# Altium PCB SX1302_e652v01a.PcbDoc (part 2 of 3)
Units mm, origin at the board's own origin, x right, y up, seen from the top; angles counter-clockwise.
Board outline 70.5 x 56 mm, 6 copper layers (Top Layer, MidLayer1 - GND, MidLayer2, MidLayer3, MidLayer4, Bottom Layer), stack 0.992 mm thick; 264 components, 191 nets, 862 pads, 1252 vias.
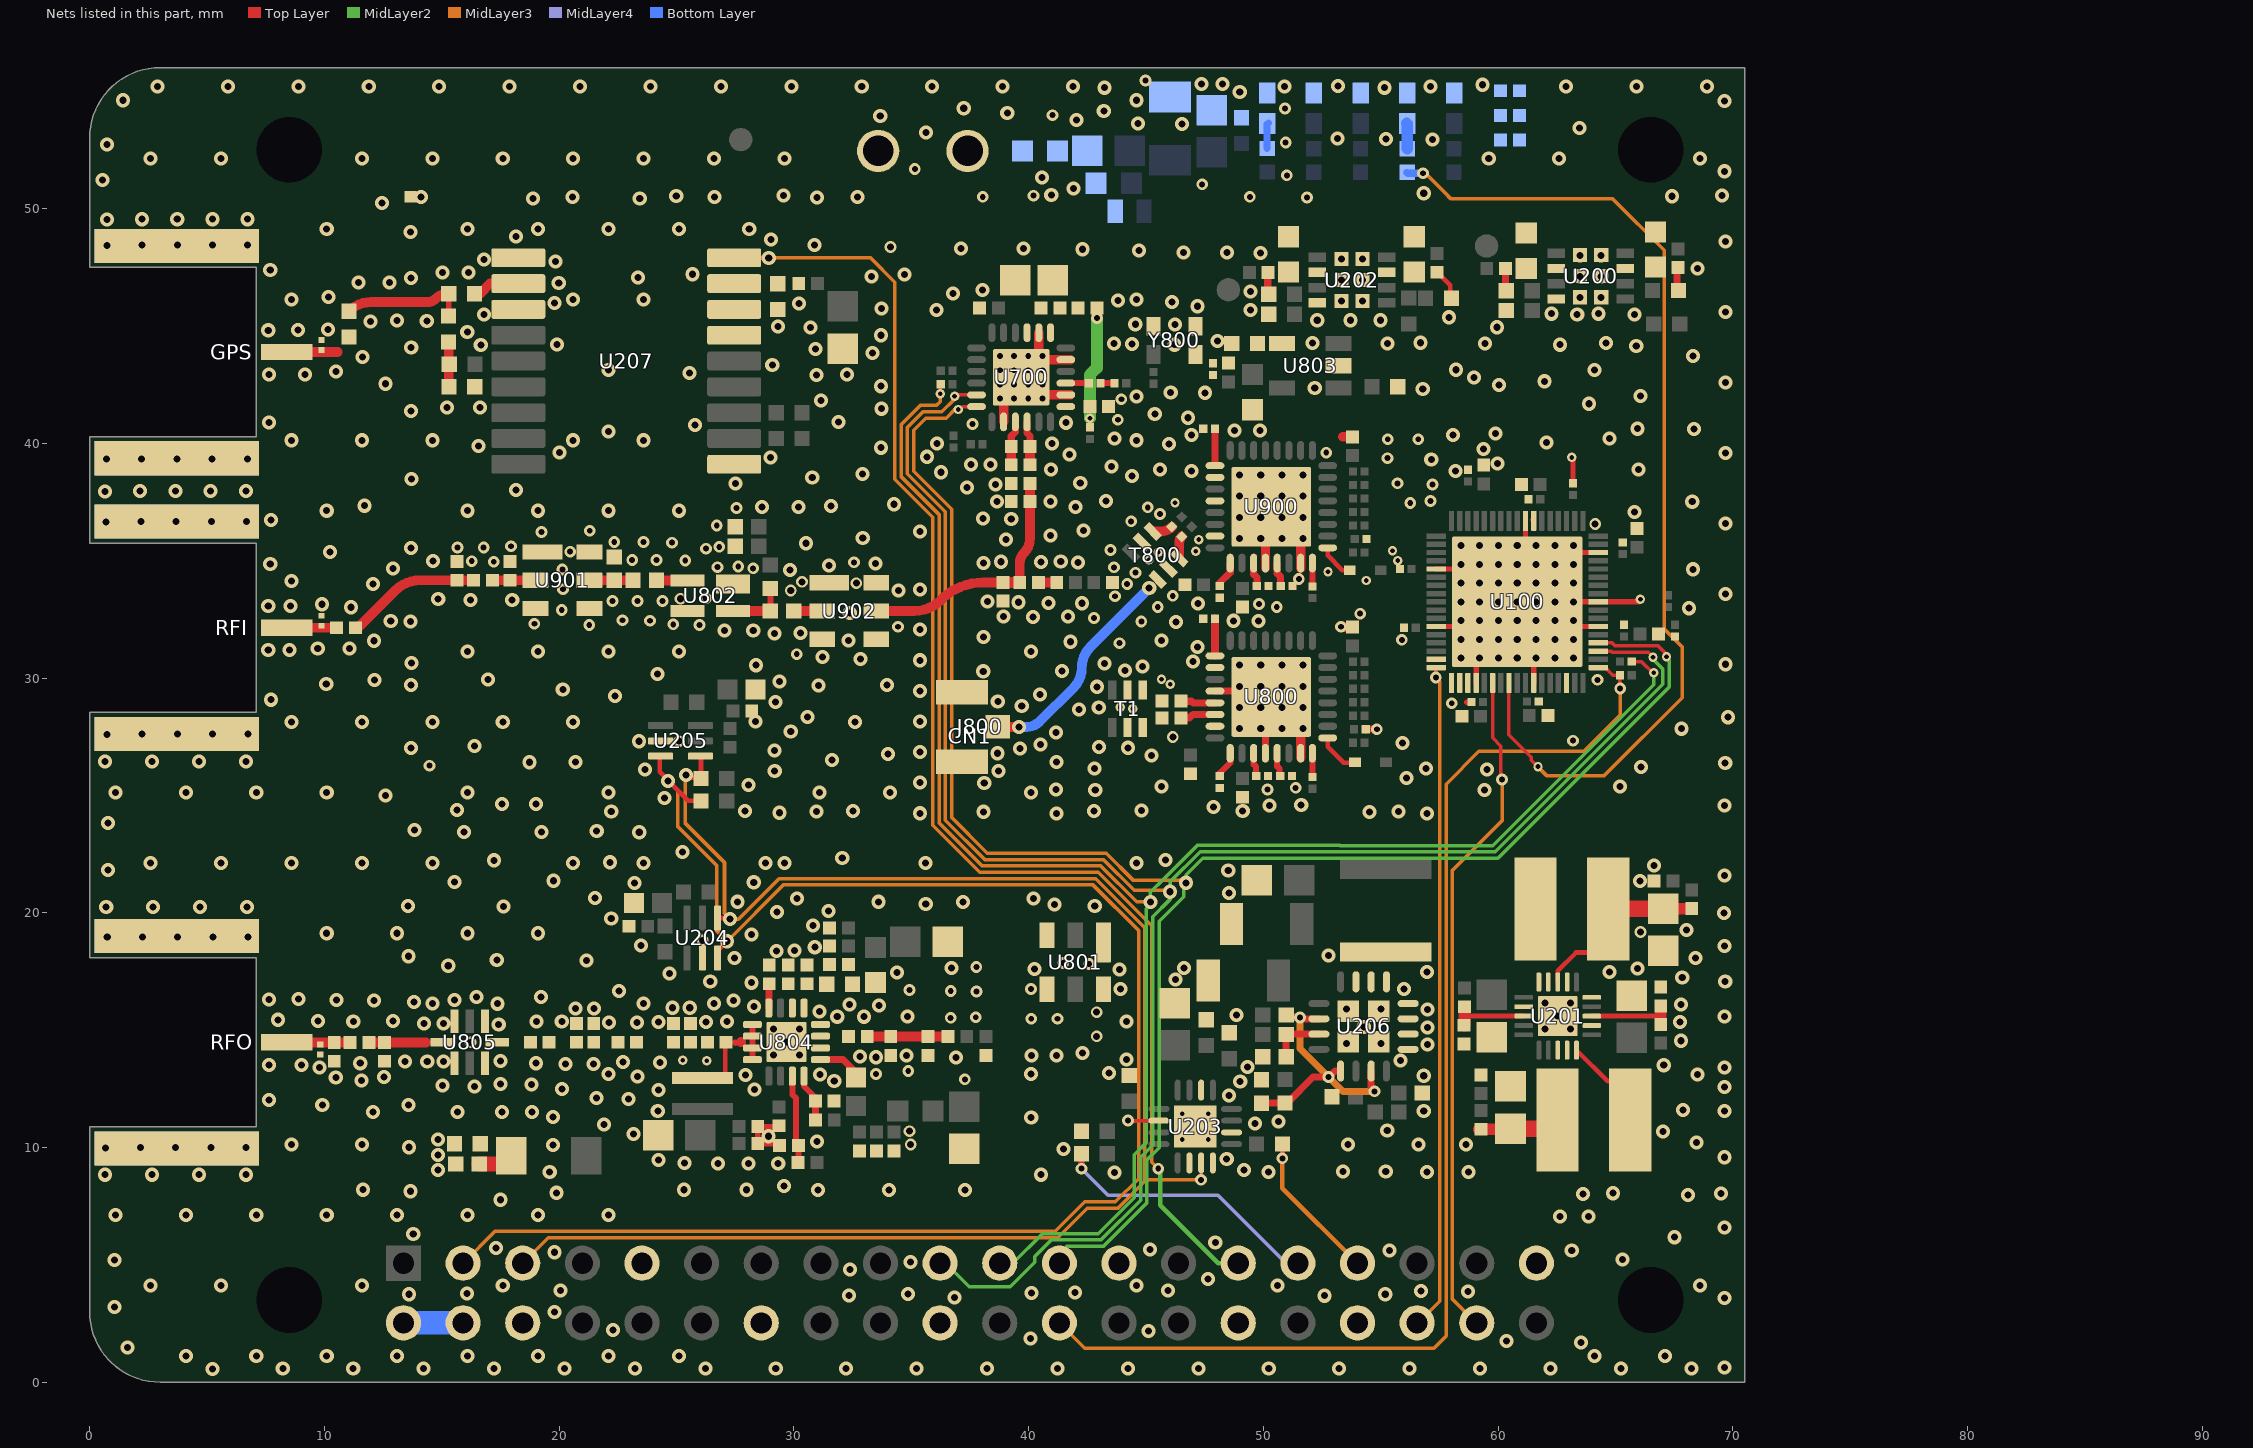
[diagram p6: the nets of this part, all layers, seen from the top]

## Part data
821M 915M Other R2 R10 R11 R12 R15 R100 R101 R102 R103 R104 R105 R106 R108 R110 R111 R112 R113 R114 R115 R120 R121 R122 R123 R124 R125 R205 R208 R209 R210 R211 R212 R214 R215 R216 R701 R702 R703 R704 R705 R713 R813 R814 R815: "Resistor SMD - IEC symbol version"
C2 C7 C8 C9 C10 C11 C12 C13 C14 C18 C19 C22 C23 C24 C25 C26 C27 C28 C31 C32 C33 C36 C37 C38 C39 C40 C41 C42 C43 C44 C45 C46 C51 C52: library part 70001226, "Ceramic Capacitor SMD"
C34 C100 C101 C102 C103 C104 C105 C106 C107 C108 C109 C110 C111 C112 C113 C201 C202 C203 C204 C212 C213 C215 C216 C217 C218 C220 C221 C222 C223 C708 C711 C712 C713 C716 C717 C718 C800 C801 C802 C803 C804 C805 C806 C807 C808 C809 C810 C813 C814 C815 C816 C838 C841 C842 C900 C901 C903 C904 C905 C906 C907 C908: "Capacitor SMD"
C35 C47 C48: library part Capacitor_p, "CAP TANT 120UF 6.3V", Manufacturer=Vishay
C200 C205 C206 C207 C209 C210 C211 C811 C812 C817: library part 70001485, "Ceramic Capacitor SMD"
C208 C219: library part Capacitor_p, "CAP TANT 10UF 6.3V", Manufacturer=Vishay
C214: library part CAP, "Ceramic Capacitor SMD"
CN1: library part RPI, "Raspberry PI 2x20p connector - Header male or receptacle"
D1 D3 D5 D802: library part RClamp0531T, "Ultra Low Capacitance 1-line ESD Protection"
D2 D800 D900: "Schottky Diode"
F200: "Fuse"
"Fiducial Mark1" "Logo ESD 1" "Logo ESD 2" "Logo LoRa 1" "Logo LoRa 2" "Logo Recycling2" "Logo Semtech 1" "Logo Semtech 2": library part Logo, "Schematic symbol for Logo"
GPS RFI RFO: "SMA Right Angle Jack, Edge Mount, Up to 18 GHz, -65 to 165 degC"
J800: library part 1909763-1, "Ultra Miniature Coaxial Connector Jack, 60 V, 50 Ohm, -40 to 90 degC, RoHS, Tape and Reel", Maximum Frequency="6 GHz", Operating Temperature Range="- 40 C to + 90 C", Supplier Part Number 1=62X0488
L1: library part L_LPS4018-102NLB, "Shielded Power Inductor 1uH isat 2.5A", Manufacturer=Coilcraft
L2 L10: library part L_MPZ1608S300A, "Ferrite Bead 30Ohm 10mOhm DC 5A", Manufacturer=TDK
L3: library part L_LQW15AN11NJ80D_11NH_0402, "Inductance wirewound 0402", Manufacturer=Murata
L4: library part L_LQW15AN8N7J80D_8_7NH_0402, "Inductance wirewound 0402", Manufacturer=Murata
L7: library part L_LQW15AN3N6D80D_3_6NH_0402, "Inductance wirewound 0402", Manufacturer=Murata
L8: library part L_FBMH4532HM681, "Ferrite Bed 680 Ohm 1812", Manufacturer="Tayio Yuden"
L11: library part L_LQW15AN1N6D80D_1_6NH_0402, "Inductance wirewound 0402", Manufacturer=Murata
L12: library part L_LQW15ANR10J00D_100NH_0402, "100nH Inductance wirewound 0402", Manufacturer=Murata
L13: library part L_LQW15AN10NJ80D_10NH_0402, "10nH Inductance wirewound 0402", Manufacturer=Murata
L15: library part L_LQW15AN3N6D80D_3_6NH_0402, "3.6nH Inductance wirewound 0402", Manufacturer=Murata
L202: "Inductor SMD"
P1: library part "Header 2", "Header, 2-Pin"
P200 P201: library part "Testpunkt SMD"
R1 R9 R13 R300: library part 70001106, "SMD Resistor"
R3 R4 R5 R6 R7 R8 R14 R19 R200 R201 R202 R203 R204 R206 R207 R213 R218 R219 R220: library part Res, "SMD Resistor"
R217: "Resistor"
"RF Shield": library part Shield, "RF Shield - EMI Gasket - Standard Surface Mount Shields"
RV1: library part RV_82536259, "Varistor 5.5V 0603", Manufacturer=Würth
T1 T800: library part T_BALUN_HHM1564A4, "High Frequency Balun - TDK HHM Series", 490MHz MPN=HHM1591D1, Manufacturer=TDK
U100: "SX1302 - Base Band Processor for Data Concentrator for Long Range Communication Network;"
U200 U202: "SC4212 - Very Low Input /Very Low Dropout  1Amp Regulator With Enable", Manufacturer=Semtech
U201: "SC284 - Dual Channel 2.5MHz, 1.8A  Synchronous Step-Down Regulator"
U204 U205: library part STTS751, "2.25 V low-voltage local digital temperature sensor"
U206: "6.5 V, 4 A, High Efficiency,   Step-Down DC-to-DC Regulator", Manufacturer="Analog Devices"
U207: library part MAX-7Q, "MAX-7Q; U-Blox; 7 GPS/GNSS modules"
U700: library part SX126x, "SX1261/2 - Ultra low power RF transceiver"
U800 U900: library part SX1257, "SX1257 RF Front-End Transceiver - I/Q New Pinout"
U801 U901 U902: "SAW Filter - Bandpass - TEMEX type"
U802: "Low Noise Amplifier", Manufacturer=RFMD
U803: library part LP2985-33, "LDO 150mA w/ Enable", Manufacturer=TI
U804: "RF5110G - General Power Amplifier", Manufacturer=RFMD
U805: library part FILT_0915LP15A026, "RF Filter - Lowpass", Manufacturer="Johanson Technology"

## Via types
v1: diameter 0.6, hole 0.3, Top Layer to Bottom Layer, tented both sides, 827 vias
v2: diameter 0.5, hole 0.25, Top Layer to Bottom Layer, tented both sides, 168 vias
v3: diameter 0.6, hole 0.3, Top Layer to Bottom Layer, tented top, 86 vias
v4: diameter 0.4, hole 0.2, Top Layer to Bottom Layer, tented both sides, 59 vias
v5: diameter 0.6, hole 0.3, Top Layer to Bottom Layer, 48 vias
v6: diameter 0.6, hole 0.3, Top Layer to Bottom Layer, tented bottom, 21 vias
v7: diameter 0.5, hole 0.3, Top Layer to Bottom Layer, tented both sides, 18 vias
v8: diameter 0.5, hole 0.25, Top Layer to Bottom Layer, tented top, 16 vias
v9: diameter 0.5, hole 0.3, Top Layer to Bottom Layer, 5 vias
v10: diameter 0.5, hole 0.2, Top Layer to Bottom Layer, 4 vias

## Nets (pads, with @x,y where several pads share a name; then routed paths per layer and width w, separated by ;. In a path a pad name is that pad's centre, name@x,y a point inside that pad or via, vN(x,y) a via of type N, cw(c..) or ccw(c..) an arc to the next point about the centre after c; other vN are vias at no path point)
AD5338R_LDAC_N: CN1.31 R219.2 | length 11.6
  Top Layer w0.25: v2(42.251,9.102) 42.252,9.104 R219.2@42.252,9.733 R219.2@42.252,9.783
  MidLayer4 w0.15: v2(42.251,9.102) 43.383,7.97 48.067,7.97 50.962,5.075 CN1.31@51.471,5.075
AD5338R_RESET_N: CN1.33 R220.2 | length 6.4
  Top Layer w0.2: v2(50.81,9.542) 50.812,9.544 R220.2@50.812,10.15
  MidLayer3 w0.2: v2(50.81,9.542) 50.81,8.276 CN1.33@54.011,5.075
CONFIG_OK: R105.2 U100.59 | length 43.8
  Top Layer w0.15: U100.59@60.449,29.825 60.449,29.798 60.449,27.59 61.414,26.625 61.414,26.497 61.681,26.23 v4(61.701,26.23)
  MidLayer3 w0.15: v2@56.78,51.505 v2(56.801,51.505) 56.801,51.424 56.841,51.465 56.891,51.515 57.701,50.705 57.995,50.411 64.881,50.411 67.072,48.22 67.072,32.093 67.838,31.326 67.838,29.161 64.525,25.848 62.063,25.848 61.701,26.211 v4(61.701,26.23) 61.681,26.23 v4@61.617,26.294
  Bottom Layer w0.3: R105.2@56.106,51.542 56.116,51.532 56.142,51.505 v2(56.801,51.505)
GND: 821M.1 821M.2 915M.1 915M.2 "RF Shield.1" C2.1 C7.1 C8.1 C9.1 C10.1 C11.1 C12.1 C13.1 C14.1 C18.1 C19.1 C22.1 C23.1 C24.1 C25.1 C28.1 C31.1 C32.1 C33.1 C34.2 C35.2 C36.1 C37.1 C38.1 C39.1 C40.1 C41.1 C42.1 C43.1 C44.1 C47.2 C48.2 C51.1 C52.1 C100.1 C101.1 C102.1 C103.1 C104.1 C105.1 C106.1 C107.1 C108.1 C109.1 C110.1 C111.1 C112.1 C113.1 C200.2 C201.2 C202.2 C203.2 C204.2 C205.2 C206.2 C207.2 C208.2 C209.2 C210.2 C211.2 C212.2 C213.2 C215.2 C216.1 C217.1 C218.2 C219.2 C220.1 C221.1 C222.2 C223.2 C712.1 C713.1 C716.1 C717.1 C718.1 C800.1 C803.1 C804.2 C805.2 C806.1 C807.1 C808.1 C811.1 C812.1 C814.2 C817.1 C838.1 C841.2 C842.2 C900.1 C903.1 C904.2 C905.2 C906.1 C907.1 C908.1 CN1.6 CN1.9 CN1.14 CN1.20 CN1.25 CN1.30 CN1.34 CN1.39 CONFIG_OK.2 D1.2 D3.2 D5.2 D802.2 DC5V.2 GPS.MP J800.1 J800.3 L13.1 L800.1 Other.1 Other.2 P1.2 R6.1 R7.1 R11.1 R12.1 R13.1 R100.1 R101.1 R202.1 R206.1 R218.1 R813.2 R814.2 RFI.MP RFO.MP RV1.1 RX_ON.2 T1.2 T1.5 T800.2 T800.5 TX_ON.2 U100.6 U100.9 U100.15 U100.24 U100.25 U100.39 U100.46 U100.55 U100.62 U100.69 U200.8 U200.9 U201.2 U201.9 U201.12 U201.15 U201.17 U201.19 U201.21 U202.8 U202.9 U203.2 U203.10 U203.12 U203.14 U203.17 U204.5 U205.5 U206.5 U206.6 U206.7 U206.8 U206.17 U207.1 U207.10 U207.12 U700.2 U700.5 U700.8 U700.20 U700.25 U800.4 U800.7 U800.26 U800.28 U800.31 U800.33 U801.1 U801.3 U801.4 U801.6 U802.2 U802.4 U803.2 U804.2 U804.4 U804.17 U805.1 U805.3 U805.5 U805.7 U900.4 U900.7 U900.26 U900.28 U900.31 U900.33 U901.1 U901.3 U901.4 U901.6 U902.1 U902.3 U902.4 U902.6 VCCIO33.2 Y800.1 Y800.2 | length 28.2
  Top Layer w0.2: U100.24@61.463,36.75 U100.24@61.515,36.698 ; v4@63.091,39.451 v4(63.141,39.4)
  Top Layer w0.23: C14.1@28.496,10.089 28.463,10.122 C14.1@28.463,10.169 ; C19.1@29.376,10.93 29.376,10.894 28.924,10.894 C13.1@28.463,10.894 C14.1@28.463,10.169 ; C2.1@29.461,10.038 29.403,10.096 29.33,10.169 28.924,10.169 C14.1@28.463,10.169 ; U100.46@57.365,32.198 58.365,32.198 U100.69@58.415,32.248 ; U100.39@57.365,34.648 U100.69@58.415,34.648 ; 58.667,28.978 C108.1@58.862,28.978 ; U100.55@59.065,29.798 U100.69@59.065,30.848 ; U100.69@61.165,35.648 U100.25@61.165,36.698 ; U100.62@61.515,29.798 U100.69@61.515,30.773 ; U100.69@63.09,32.198 63.215,32.198 U100.6@64.265,32.198 ; U100.69@63.115,35.348 63.215,35.348 U100.15@64.265,35.348 ; v4@63.182,39.458 63.19,39.45 63.192,39.448 63.192,39.4 R100.1@63.192,38.303 ; U100.69@63.326,33.255 63.333,33.248 U100.9@64.265,33.248 65.994,33.248 v4@66.001,33.255
  Top Layer w0.3: U800.28@47.939,29.448 48.989,29.448 49.889,29.448 50.089,29.448 U800.33@50.339,29.198 ; U800.4@50.089,26.798 50.089,27.848 U800.33@50.089,27.948 ; U800.33@51.639,29.423 U800.33@51.664,29.448 ; U800.33@51.664,28.923 U800.33@51.689,28.948 ; R813.2@54.364,27.798 54.377,27.811 54.389,27.823 v2@54.664,27.823
  Top Layer w0.4: U700.20@38.935,40.914 38.935,41.914 U700.25@38.935,41.939 ; U700.25@40.41,43.564 40.585,43.564 U700.5@41.585,43.564 U700.5@41.785,43.564 ; U700.25@40.41,43.714 40.435,43.739 U700.8@40.435,44.714 ; U700.25@40.585,42.064 U700.2@41.585,42.064 U700.2@41.785,42.064 ; U900.4@50.089,34.698 U900.4@50.089,34.898 50.089,35.948 U900.33@50.089,36.25 ; U800.33@51.539,27.898 51.589,27.848 U800.7@51.589,26.798 U800.7@51.589,26.598 ; U900.33@51.539,35.998 51.589,35.948 U900.7@51.589,34.898 U900.7@51.589,34.673 ; v2@53.389,32.173 C800.1@53.789,32.173 ; 53.389,40.273 C900.1@53.789,40.273
  other v1: 5.229,0.564 8.229,0.589 11.229,0.589 14.229,0.589 17.229,0.589 20.229,0.589 23.229,0.589 26.229,0.589 29.229,0.589 32.229,0.589 35.229,0.589 38.229,0.589 41.229,0.589 44.229,0.589 47.229,0.589 50.229,0.589 53.229,0.589 56.229,0.589 59.229,0.589 62.229,0.589 65.229,0.589 68.229,0.589 69.644,0.64 4.101,1.13 7.101,1.13 10.101,1.13 13.101,1.13 16.101,1.13 19.101,1.13 22.101,1.13 25.101,1.13 64.101,1.13 67.101,1.13 1.623,1.478 63.527,1.702 60.363,1.767 40.072,1.862 45.108,2.195 22.292,2.222 19.809,3.002 1.064,3.205 69.644,3.589 36.843,3.614 32.352,3.694 52.602,3.69 13.6,3.754 55.192,3.754 16.071,3.781 34.87,3.767 40.118,3.805 41.984,3.819 56.712,3.888 58.725,3.87 20.06,3.908 45.934,3.92 2.601,4.13 5.601,4.13 11.601,4.13 17.601,4.13 44.601,4.13 50.601,4.13 68.601,4.13 47.639,4.409 32.393,4.805 34.973,5.127 1.064,5.205 65.301,5.236 19.807,5.541 55.373,5.617 63.137,5.624 45.178,5.652 17.318,5.719 47.952,5.955 67.512,6.182 13.787,6.313 69.644,6.589 62.633,7.066 63.853,7.066 1.101,7.13 4.101,7.13 7.101,7.13 10.101,7.13 13.101,7.13 16.101,7.13 19.101,7.13 22.101,7.13 17.498,7.777 63.624,8.031 64.894,8.057 11.649,8.206 25.328,8.204 27.989,8.204 31.02,8.201 34.054,8.201 37.284,8.201 29.579,8.36 0.657,8.844 2.657,8.844 4.657,8.844 6.657,8.844 40.522,8.844 43.654,8.937 19.6,8.963 50.213,8.958 56.963,8.966 58.73,8.966 53.398,8.976 55.214,8.976 49.175,9.043 26.769,9.327 28.064,9.327 29.334,9.327 25.346,9.352 24.229,9.475 48.439,9.517 69.644,9.589 41.491,9.946 19.733,10.103 8.601,10.13 11.601,10.13 53.601,10.13 56.601,10.13 58.625,10.132 68.454,10.21 30.987,10.267 28.924,10.484 23.162,10.571 67.03,10.69 55.277,10.723 21.917,10.978 49.636,11.035 50.64,11.108 40.111,11.281 19.733,11.308 12.064,11.525 15.669,11.525 17.573,11.525 18.853,11.51 24.203,11.562 56.832,11.562 67.869,11.604 9.912,11.81 13.586,11.816 7.651,12.019 22.953,12.063 21.587,12.121 48.532,12.222 24.229,12.451 28.318,12.476 20.123,12.502 69.644,12.589 16.397,12.607 15.033,12.654 18.818,12.68 17.498,12.705 49.014,12.822 31.721,12.835 11.579,12.857 10.487,12.984 12.545,13.01 23.34,13.035 56.832,13.06 27.937,13.086 22.101,13.13 31.119,13.118 40.101,13.13 68.501,13.112 43.416,13.186 9.802,13.416 49.321,13.437 67.056,13.509 7.642,13.518 9.02,13.521 20.267,13.559 21.459,13.557 11.529,13.594 19.022,13.594 24.305,13.619 22.73,13.645 13.433,13.675 14.383,13.675 15.069,13.675 17.498,13.696 55.835,13.714 44.174,13.757 36.914,13.835 33.5,13.848 32.814,13.873 34.807,13.919 41.193,13.915 40.118,13.926 42.291,14.033 56.993,14.388 67.792,14.551 56.99,15.124 17.427,15.245 14.251,15.293 15.069,15.286 22.119,15.335 23.313,15.337 11.232,15.367 19.041,15.365 20.114,15.365 24.233,15.354 26.261,15.354 67.754,15.354 27.155,15.372 44.174,15.372 9.733,15.398 12.926,15.397 8.026,15.445 31.849,15.575 32.992,15.575 34.849,15.583 69.644,15.589 48.847,15.655 31.087,15.804 56.99,15.886 20.698,15.924 21.478,15.933 24.83,15.958 25.566,15.958 28.298,16.007 33.631,16.052 32.379,16.099 67.792,16.1 14.601,16.13 17.371,16.128 23.601,16.13 26.601,16.13 13.827,16.203 12.113,16.261 27.428,16.274 10.518,16.288 15.542,16.286 7.651,16.314 8.902,16.329 16.477,16.408 19.233,16.417 22.552,16.667 43.911,16.759 55.99,16.763 28.203,17.023 26.438,17.074 46.251,17.156 67.843,17.243 24.706,17.418 34.393,17.462 56.963,17.472 64.744,17.472 43.881,17.582 40.256,17.607 65.938,17.624 36.723,17.642 46.622,17.649 15.278,17.747 21.164,17.97 17.345,17.988 27.466,18.078 68.403,18.078 13.586,18.151 52.769,18.191 29.255,18.366 30.029,18.397 30.892,18.536 69.644,18.589 23.492,18.607 28.203,19.081 10.101,19.13 13.101,19.13 16.101,19.13 19.101,19.13 68.034,19.264 30.807,19.461 22.222,19.76 29.287,20.039 31.47,20.078 0.708,20.249 2.708,20.249 4.708,20.249 6.708,20.249 17.625,20.274 42.818,20.287 41.112,20.348 35.619,20.384 27.607,20.471 33.601,20.471 37.197,20.457 30.126,20.615 40.205,20.604 21.536,20.63 48.529,20.843 23.214,21.263 28.292,21.302 15.542,21.316 66.04,21.358 19.758,21.366 69.644,21.589 48.504,21.797 0.784,21.824 66.649,22.018 28.798,22.126 2.601,22.13 5.601,22.13 8.601,22.13 11.601,22.13 14.601,22.13 20.601,22.13 23.601,22.13 29.601,22.13 35.601,22.13 44.601,22.13 22.171,22.154 17.229,22.239 45.834,22.254 32.062,22.332 25.256,22.584 23.415,23.433 15.948,23.449 19.25,23.449 13.84,23.525 0.784,23.824 41.184,24.231 56.963,24.231 35.376,24.241 29.383,24.264 38.078,24.305 54.513,24.29 22.222,24.313 30.957,24.313 55.76,24.313 27.922,24.338 32.516,24.338 42.788,24.338 44.803,24.36 49.121,24.338 15.643,24.389 47.876,24.516 50.264,24.567 69.649,24.575 51.613,24.592 17.574,24.643 19.022,24.643 24.487,24.886 12.602,25.006 1.101,25.13 4.101,25.13 7.101,25.13 10.101,25.13 16.101,25.13 22.101,25.13 31.101,25.13 34.101,25.13 40.101,25.13 41.159,25.248 42.839,25.228 59.428,25.236 45.66,25.38 65.199,25.38 28.064,25.44 35.376,25.544 38.11,25.534 56.091,25.751 38.722,26.037 29.185,26.043 23.665,26.098 59.53,26.098 42.809,26.142 56.931,26.142 66.088,26.218 18.731,26.414 20.698,26.421 41.189,26.426 0.657,26.446 2.657,26.446 4.657,26.446 6.657,26.446 31.633,26.507 45.234,26.7 34.007,26.763 38.668,26.798 35.376,26.848 29.171,26.923 39.632,26.998 44.233,27.032 43.005,27.072 16.393,27.099 40.502,27.163 55.928,27.234 23.399,27.31 41.159,27.674 29.868,27.716 67.815,27.843 8.601,28.13 11.601,28.13 14.601,28.13 17.601,28.13 20.601,28.13 28.372,28.145 32.601,28.13 35.376,28.152 30.585,28.337 69.798,28.334 42.15,28.653 42.99,28.748 39.707,28.802 29.215,28.986 38.687,29.005 7.733,29.079 22.374,29.23 40.479,29.297 35.376,29.455 20.157,29.522 42.91,29.63 31.051,29.684 13.688,29.698 33.971,29.698 10.081,29.748 29.392,29.846 12.138,29.926 16.977,29.948 24.193,30.182 38.068,30.29 41.414,30.306 44.11,30.326 44.851,30.486 28.384,30.548 69.695,30.589 43.228,30.615 13.713,30.637 47.001,30.707 35.376,30.759 32.839,30.815 31.214,30.891 16.101,31.13 19.101,31.13 22.101,31.13 25.101,31.13 40.101,31.13 7.61,31.205 8.523,31.195 9.719,31.262 11.071,31.257 47.19,31.323 41.779,31.548 12.112,31.59 32.331,31.603 45.659,31.603 38.078,31.755 29.176,31.905 30.281,31.925 27.048,32.025 28.27,32.025 35.376,32.063 46.276,32.39 12.829,32.424 13.662,32.415 49.789,32.425 48.723,32.441 40.182,32.611 38.935,32.623 41.679,32.623 32.382,32.771 68.139,32.976 11.136,33.018 7.61,33.071 8.555,33.071 9.896,33.146 47.214,33.173 42.268,33.187 40.852,33.204 39.565,33.231 38.257,33.27 16.228,33.32 18.003,33.325 14.851,33.363 69.695,33.589 34.465,33.727 35.376,33.771 12.073,34.001 8.601,34.13 29.843,34.611 68.302,34.635 12.926,34.676 31.493,34.803 7.695,34.865 33.474,34.879 38.085,34.902 40.522,34.95 42.099,34.93 38.822,34.955 41.37,34.968 14.628,34.98 10.232,35.378 13.688,35.54 30.526,35.743 39.043,35.904 32.935,35.973 40.935,36.08 35.376,36.25 42.345,36.296 69.695,36.589 7.733,36.733 39.26,36.771 38.063,36.794 65.803,37.076 10.101,37.13 16.101,37.13 19.101,37.13 22.101,37.13 25.101,37.13 42,37.282 28.648,37.292 30.198,37.292 31.583,37.328 11.706,37.343 34.261,37.405 40.935,37.514 68.269,37.513 38.656,37.523 43.296,37.548 0.657,37.957 2.154,37.967 3.654,37.967 5.154,37.967 6.654,37.967 18.156,38.017 37.371,38.111 38.591,38.25 27.509,38.295 42.199,38.304 30.784,38.553 44.396,38.613 32.924,38.69 36.26,38.768 46.93,38.814 58.188,38.814 40.949,38.889 65.972,38.881 45.59,38.892 43.529,39.019 37.538,39.105 38.374,39.105 59.971,39.149 57.153,39.313 29.008,39.399 35.672,39.428 41.743,39.519 69.695,39.589 20.022,39.604 59.372,39.761 33.719,39.813 16.567,39.891 45.98,39.979 36.103,39.996 40.991,39.996 62.055,40.033 8.601,40.13 11.601,40.13 14.601,40.13 20.601,40.13 23.601,40.13 44.601,40.13 43.658,40.199 64.737,40.199 46.93,40.363 58.07,40.349 59.885,40.424 22.097,40.505 48.765,40.543 49.857,40.543 68.346,40.606 65.943,40.623 25.788,40.774 7.642,40.882 41.6,40.878 31.906,40.914 46.782,41.09 45.375,41.258 33.739,41.474 15.223,41.534 16.639,41.534 63.878,41.686 31.151,41.829 44.602,41.995 66.062,42.017 47.515,42.154 46.053,42.172 56.789,42.319 52.19,42.36 33.715,42.433 60.047,42.493 12.596,42.539 69.695,42.589 61.976,42.643 58.976,42.804 30.963,42.912 7.651,42.933 9.179,42.933 32.266,42.933 25.553,42.991 10.503,43.058 22.101,43.13 64.101,43.13 58.214,43.134 29.081,43.33 11.624,43.674 68.302,43.721 33.353,43.852 30.928,44.019 65.885,44.15 16.664,44.188 19.915,44.216 46.213,44.201 62.633,44.201 43.642,44.247 44.402,44.233 55.296,44.25 59.433,44.252 52.089,44.281 56.691,44.285 64.589,44.277 48.042,44.355 33.715,44.605 16.088,44.746 7.61,44.816 8.871,44.829 10.163,44.854 30.701,44.937 59.945,44.945 29.325,44.981 46.236,45.054 44.544,45.073 11.973,45.198 14.364,45.205 13.102,45.226 52.296,45.242 53.718,45.242 54.988,45.242 57.909,45.369 16.8,45.486 65.806,45.486 63.37,45.496 62.278,45.522 64.284,45.522 69.695,45.589 36.08,45.68 49.451,45.674 33.739,45.752 47.19,45.841 30.221,45.965 19.807,45.987 46.114,46.022 43.8,46.089 8.601,46.13 20.601,46.13 23.601,46.13 44.601,46.13 10.182,46.235 36.78,46.39 49.445,46.47 38.035,46.523 19.984,46.822 11.456,46.843 12.773,46.856 23.369,47.069 33.302,47.1 25.68,47.203 34.706,47.2 15.033,47.274 16.141,47.274 7.695,47.385 68.501,47.452 19.849,47.749 16.796,47.825 49.882,48.114 46.591,48.138 48.45,48.138 44.697,48.222 42.291,48.268 37.119,48.292 39.777,48.295 30.883,48.445 69.695,48.589 29.026,48.685 18.156,48.813 10.101,49.13 16.101,49.13 19.101,49.13 22.101,49.13 25.101,49.13 28.101,49.13 0.737,49.537 2.234,49.547 3.734,49.547 5.234,49.547 6.734,49.547 12.459,50.233 23.436,50.437 14.119,50.5 20.571,50.5 26.616,50.5 32.712,50.5 67.409,50.526 29.556,50.556 69.542,50.551 40.966,50.576 41.907,50.856 0.556,51.211 40.565,51.328 69.644,51.589 2.601,52.13 5.601,52.13 11.601,52.13 14.601,52.13 17.601,52.13 20.601,52.13 23.601,52.13 26.601,52.13 29.601,52.13 59.601,52.13 62.601,52.13 68.601,52.13 0.734,52.735 57.198,52.939 55.217,52.964 53.159,52.989 35.637,53.233 63.458,53.44 46.53,53.609 44.658,53.631 42.038,53.767 33.681,53.945 39.091,54.072 43.202,54.158 37.237,54.275 69.644,54.589 1.419,54.615 44.601,54.615 48.994,54.971 43.228,55.148 55.166,55.148 2.893,55.199 5.893,55.199 8.893,55.199 11.893,55.199 14.893,55.199 17.893,55.199 20.893,55.199 23.893,55.199 26.893,55.199 29.893,55.199 32.893,55.199 35.893,55.199 38.893,55.199 41.893,55.199 50.893,55.199 57.122,55.199 62.893,55.199 65.893,55.199 68.893,55.199 53.185,55.225 59.331,55.275 47.368,55.301 48.257,55.301
  other v2: 37.284,12.908 33.5,13.137 34.876,13.259 40.111,15.489 41.232,15.489 36.68,15.528 37.746,15.553 37.78,16.645 36.682,16.674 34.922,16.718 40.104,16.76 37.774,17.691 42.584,17.824 41.477,17.86 50.18,25.25 51.377,25.324 14.475,26.269 63.192,27.335 54.836,27.818 58.023,28.928 64.234,29.926 30.121,31.018 43.872,31.488 55.901,31.63 34.439,32.187 53.312,32.187 21.282,32.263 25.981,32.263 24.864,32.288 18.945,32.314 44.803,32.407 23.873,32.441 22.705,32.466 42.785,32.559 54.124,32.746 20.114,32.898 45.5,33.025 50.568,33.028 49.811,33.158 22.273,33.279 23.34,33.279 24.406,33.279 43.685,33.487 46.14,33.503 20.165,33.787 44.199,34.008 51.511,34.225 44.553,34.493 20.139,34.625 28.267,34.676 43.634,34.718 26.743,34.727 27.632,34.752 32.56,34.93 17.218,34.955 16.278,34.981 25.372,35.006 23.111,35.032 24.152,35.032 20.469,35.387 43.484,35.455 26.261,35.514 15.669,35.565 16.786,35.565 26.819,35.59 17.955,35.616 24.813,35.768 22.349,35.794 23.594,35.794 19.25,36.225 21.308,36.276 26.718,36.505 44.369,36.678 45.598,36.989 27.556,37.241 45.074,37.273 56.258,37.456 57.122,37.548 57.204,38.25 55.711,38.295 55.285,39.368 52.677,39.604 55.3,40.176 56.601,40.176 37.61,40.82 43.802,41.007 43.951,41.879 51.864,50.475 38.046,50.5 49.425,50.5 40.205,50.551 47.393,51.034 51,51.415 35.154,51.684 50.949,52.812 41.018,53.98 50.924,54.259 44.98,55.453
  other v3: 61.989,15.052 63.089,15.052 62.539,15.602 61.989,16.152 63.089,16.152 48.989,27.848 49.889,27.848 50.789,27.848 51.689,27.848 48.989,28.748 49.889,28.748 50.789,28.748 51.689,28.748 48.989,29.648 49.889,29.648 50.789,29.648 51.689,29.648 48.989,30.548 49.889,30.548 50.789,30.548 51.689,30.548 58.415,30.848 59.215,30.848 60.015,30.848 60.815,30.848 61.615,30.848 62.415,30.848 63.215,30.848 58.415,31.648 59.215,31.648 60.015,31.648 60.815,31.648 61.615,31.648 62.415,31.648 63.215,31.648 58.415,32.448 59.215,32.448 60.015,32.448 60.815,32.448 61.615,32.448 62.415,32.448 63.215,32.448 58.415,33.248 59.215,33.248 60.015,33.248 60.815,33.248 61.615,33.248 62.415,33.248 63.215,33.248 58.415,34.048 59.215,34.048 60.015,34.048 60.815,34.048 61.615,34.048 62.415,34.048 63.215,34.048 58.415,34.848 59.215,34.848 60.015,34.848 60.815,34.848 61.615,34.848 62.415,34.848 63.215,34.848 58.415,35.648 59.215,35.648 60.015,35.648 60.815,35.648 61.615,35.648 62.415,35.648 63.215,35.648 48.989,35.948 49.889,35.948 50.789,35.948 51.689,35.948 48.989,36.848 49.889,36.848 50.789,36.848 51.689,36.848 48.989,37.748 49.889,37.748 50.789,37.748 51.689,37.748 48.989,38.648 49.889,38.648 50.789,38.648 51.689,38.648
  other v4: 26.286,13.696 25.27,13.721 44.435,28.697 43.898,28.756 46.036,29.744 45.659,29.948 66.062,33.363 54.382,34.158 52.753,34.524 45.117,35.029 55.726,35.005 45.529,35.36 47.12,35.398 55.501,35.43 47.252,35.901 46.236,37.466
  other v5: 0.67,9.991 2.167,10.001 3.667,10.001 5.167,10.001 6.667,10.001 53.541,14.429 55.014,14.429 54.277,15.14 53.541,15.902 55.014,15.902 0.752,18.964 2.249,18.974 3.749,18.974 5.249,18.974 6.749,18.974 0.744,27.603 2.241,27.613 3.741,27.613 5.241,27.613 6.741,27.613 0.692,36.658 2.189,36.668 3.689,36.668 5.189,36.668 6.689,36.668 0.721,39.328 2.218,39.338 3.718,39.338 5.218,39.338 6.718,39.338 53.337,46.055 54.226,46.055 63.497,46.208 64.386,46.208 53.337,46.957 54.226,46.957 63.497,47.109 64.386,47.109 53.337,47.859 54.226,47.859 63.497,48.011 64.386,48.011 0.739,48.435 2.236,48.445 3.736,48.445 5.236,48.445 6.736,48.445 56.832,50.653
  other v6: 68.088,7.985 69.492,8.051 19.883,8.075 13.666,8.141 13.6,10.014 69.649,11.562 69.644,13.418 69.674,17.081 69.616,19.997 13.561,20.287 21.603,23.485 69.674,26.382 13.688,27.017 13.708,38.482 13.693,41.371 13.701,44.083 13.688,47.037 13.677,49.006 18.883,50.432 30.989,50.475 24.99,50.541
  other v7: 34.977,10.127 34.922,10.698 16.226,14.485 42.901,14.738 42.901,15.77 26.108,18.831 66.071,19.188 25.112,27.313 46.145,27.491 25.168,33.381 26.261,33.406 29.868,33.727 32.661,34.041 30.351,34.103 64.134,36.565 34.114,48.364
  other v8: 38.785,41.914 39.385,41.914 39.985,41.914 40.585,41.914 38.785,42.514 39.385,42.514 39.985,42.514 40.585,42.514 38.785,43.114 39.385,43.114 39.985,43.114 40.585,43.114 38.785,43.714 39.385,43.714 39.985,43.714 40.585,43.714
  other v9: 29.135,13.945 30.235,13.945 29.685,14.495 29.135,15.045 30.235,15.045
  other v10: 46.55,10.347 47.65,10.347 46.55,11.447 47.65,11.447
GPIO(0): U100.66
GPIO(6): CN1.38 U100.57 | length 28.8
  Top Layer w0.15: U100.57@59.765,29.798 59.765,27.454 60.119,27.101 60.119,25.735 v2(60.17,25.684)
  MidLayer3 w0.15: CN1.38@59.107,2.484 59.073,2.518 58.056,3.535 58.056,21.818 60.17,23.932 v2(60.17,25.684)
GPIO(7): U100.54
GPIO(8): U100.53
GPIO(9): U100.52
GPIO(10): CN1.36 U100.51 | length 28.4
  Top Layer w0.15: v2(57.348,30.02) 57.348,30.431 U100.51@57.365,30.448
  MidLayer3 w0.15: CN1.36@56.541,2.484 56.571,2.514 57.506,3.449 57.506,29.862 v2(57.348,30.02)
GPIO(11): U100.50
GPS_RSTn: CN1.29 U207.9 | length 58.7
  Top Layer w0.2: U207.9@27.461,47.905 28.926,47.905 v1(28.931,47.899)
  MidLayer2 w0.2: v2(45.524,9.104) 45.547,9.104 45.612,9.168 45.612,9.104 45.612,7.546 48.083,5.075 CN1.29@48.931,5.075
  MidLayer3 w0.15: v1(28.931,47.899) 33.267,47.899 34.297,46.869 34.297,38.475 35.916,36.856 35.916,23.725 37.914,21.727 42.969,21.727 45.25,19.446 45.25,9.381 45.524,9.106 v2(45.524,9.104)
HOST_CSN: CN1.24 R103.1 U100.1 | length 52
  Top Layer w0.15: U100.1@64.265,30.448 64.565,30.448 64.89,30.123 R103.1@65.19,30.123 65.19,29.569 v2(65.199,29.56)
  MidLayer3 w0.15: CN1.24@41.311,2.535 42.387,1.458 57.268,1.458 57.786,1.976 57.786,25.485 59.179,26.878 63.649,26.878 65.199,28.429 v2(65.199,29.56)
HOST_MISO: CN1.21 R102.2 R704.2 | length 77.9
  Top Layer w0.15: v4(36.231,42.111) 36.231,42.485 R704.2@36.26,42.514 ; R102.2@65.69,30.703 66.11,30.703 66.609,30.205 66.625,30.188 v4(66.625,30.221)
  MidLayer2 w0.15: CN1.21@38.771,5.075 39.329,5.075 40.589,6.335 42.966,6.335 44.502,7.871 44.502,9.701 45.02,10.219 45.02,20.173 45.111,20.264 45.111,20.391 v1(45.187,20.467) 45.187,20.874 45.756,21.442 ; 45.756,21.443 47.183,22.87 53.262,22.87 53.267,22.865 59.769,22.865 66.625,29.721 v4(66.625,30.221)
  MidLayer3 w0.15: v4(36.231,42.111) 36.231,41.777 36.066,41.613 35.392,41.613 34.567,40.788 34.567,38.587 36.186,36.968 36.186,23.837 38.026,21.997 43.081,21.997 44.61,20.467 v1(45.187,20.467) ; v1@45.111,20.569 45.2,20.48 v1@45.213,20.467
HOST_MOSI: CN1.19 U100.3 U700.17 | length 84.8
  Top Layer w0.15: v4@36.852,42.007 36.909,42.064 U700.17@37.785,42.064 U700.17@37.807,42.064 ; U100.3@64.265,31.148 64.815,31.148 64.865,31.098 66.389,31.098 v4(66.596,30.891)
  MidLayer2 w0.15: CN1.19@36.231,5.075 36.475,5.075 37.474,4.077 39.214,4.077 40.26,5.122 40.26,5.36 40.964,6.065 43.078,6.065 44.772,7.759 44.772,9.589 45.29,10.107 45.29,19.834 46.026,20.569 v1(46.026,20.899) 46.026,21.32 47.306,22.6 53.15,22.6 53.155,22.595 59.881,22.595 67.02,29.734 67.02,30.385 66.596,30.809 v4(66.596,30.891)
  MidLayer3 w0.15: v4(36.847,42.004) 36.847,41.891 36.299,41.343 35.504,41.343 34.837,40.676 34.837,38.699 36.456,37.08 36.456,23.949 38.134,22.271 38.683,22.271 38.687,22.267 43.193,22.267 44.495,20.964 45.961,20.964 v1(46.026,20.899)
HOST_SCK: CN1.23 U100.4 U700.18 | length 79.1
  Top Layer w0.15: v4(37.004,41.442) 37.078,41.442 37.2,41.564 U700.18@37.785,41.564 ; U100.4@64.265,31.498 64.854,31.498 64.984,31.368 66.815,31.368 67.173,31.01 v4(67.173,30.911)
  MidLayer2 w0.15: CN1.23@41.311,5.472 41.626,5.788 43.182,5.788 45.042,7.647 45.042,9.477 45.56,9.995 45.56,19.647 46.604,20.691 46.604,21.097 v1@46.737,21.229 ; v1@46.711,21.255 v1(46.711,21.28) 46.711,21.624 47.418,22.33 53.038,22.33 53.043,22.325 59.993,22.325 67.29,29.622 67.29,30.794 v4(67.173,30.911)
  MidLayer3 w0.15: v4(37.004,41.442) 36.854,41.442 36.485,41.073 35.616,41.073 35.107,40.564 35.107,38.811 36.726,37.192 36.726,24.061 38.246,22.541 43.301,22.541 44.445,21.396 46.595,21.396 v1(46.711,21.28)
I2C_SCL: CN1.5 R2.1 U203.11 U204.1 U205.1 | length 70.3
  Top Layer w0.15: v2@47.35,8.732 U203.11@47.35,9.347
  Top Layer w0.2: v1@25.426,25.903 25.579,25.751 26.045,25.751 26.045,26.631 U205.1@26.011,26.664 ; U204.1@26.752,19.779 27.234,19.779 v1(27.281,19.731)
  MidLayer3 w0.15: CN1.5@18.451,5.288 CN1.5@18.451,5.075 19.538,6.162 41.247,6.162 42.502,7.418 43.809,7.418 44.955,8.563 44.955,8.621 ; v1(25.401,25.878) 25.365,25.842 25.365,23.824 27.046,22.144 27.046,19.984 27.281,19.748 v1(27.281,19.731) 27.285,19.728 27.641,19.728 29.369,21.457 42.857,21.457 44.955,19.359 44.955,8.621 ; v2(47.349,8.626) 44.959,8.626 44.955,8.621
I2C_SDA: CN1.3 R15.1 U203.6 U204.6 U205.6 | length 73.8
  Top Layer w0.15: v2@44.287,11.147 U203.6@45.55,11.147
  Top Layer w0.2: U205.6@24.283,26.665 24.283,26.005 24.651,25.636 25.507,24.781 26.045,24.781 R15.1@26.087,24.823 ; U204.6@26.752,18.079 26.752,18.387 v1(27.155,18.79)
  MidLayer3 w0.15: CN1.3@15.911,5.075 17.268,6.432 41.135,6.432 42.39,7.688 43.698,7.688 44.685,8.675 44.685,11.144 ; v1@24.588,25.725 24.639,25.674 v1(24.639,25.624) 25.045,25.217 25.045,23.692 26.726,22.011 26.726,19.225 v1@27.089,18.861 ; v1(27.155,18.79) 29.552,21.187 42.745,21.187 44.685,19.247 44.685,11.144 ; v2@44.328,11.056 44.236,11.149 44.679,11.15 44.685,11.144
  other v2: 44.236,11.15
NetC2_2: C2.2 R1.1 U804.15 | length 3.7
  Top Layer w0.25: U804.15@29.935,13.045 29.935,12.261 30.096,12.1 30.096,10.167 C2.2@30.184,10.078 ; R1.1@30.176,9.444 30.191,9.459 C2.2@30.191,10.085
NetC7_2: C7.2 R3.1 U206.15 | length 2.7
  Top Layer w0.3: R3.1@50.845,14.844 50.853,14.836 50.97,14.836 U206.15@52.368,14.836 ; R3.1@50.97,14.819 C7.2@50.97,13.869 50.97,13.794 C7.2@51.045,13.719
NetC11_2: C11.2 R4.2 R8.1 U206.1 U206.3 U206.14 | length 11
  Top Layer w0.3: C11.2@49.92,11.894 50.927,11.894 50.995,11.894 R8.1@51.02,11.919 ; R8.1@51.045,11.919 51.045,11.934 52.118,13.007 v2(52.779,13.007) ; R4.2@51.204,15.572 51.56,15.572 51.61,15.572 51.697,15.486 U206.14@52.368,15.486 ; v2@52.804,13.007 53.058,13.261 U206.1@53.293,13.261 ; v2@54.593,12.59 U206.3@54.593,13.261
  MidLayer3 w0.3: v2(51.56,15.547) 51.56,14.226 v2(52.779,13.007) 53.388,12.397 v2(54.735,12.397)
NetC18_2: C18.2 R9.1 U804.16 | length 1.9
  Top Layer w0.25: U804.16@30.435,13.045 30.435,12.619 C18.2@30.883,12.17
  Top Layer w0.3: R9.1@30.913,11.171 30.915,11.174 C18.2@30.915,11.99
NetC26_1: C26.1 U805.4
NetC26_2: C26.2 C28.2 C32.2 L7.2
NetC27_1: C27.1 U804.3 | length 0
  Top Layer w0.25: C27.1@32.387,14.745 C27.1@32.405,14.762
NetC27_2: C27.2 R10.1 R12.2 R13.2 | length 3.5
  Top Layer w0.25: R10.1@36.573,14.749 R10.1@36.577,14.752
  Top Layer w0.42: C27.2@33.126,14.73 R13.2@34.126,14.73 R12.2@35.716,14.73 36.541,14.73 36.554,14.742 R10.1@36.566,14.755
NetC31_2: C31.2 C33.2 L7.1 R300.1
NetC34_1: C34.1 CN1.2 CN1.4 FB3.1 | length 2.7
  Bottom Layer w1: CN1.2@13.371,2.535 15.882,2.535 15.897,2.521 CN1.4@15.99,2.427
  other v1: 14.846,9.043 14.846,9.692 14.846,10.341
NetC36_2: C36.2 U804.8 | length 1
  Top Layer w0.3: U804.8@28.935,15.945 28.935,16.903 C36.2@28.953,16.921
NetC40_2: C40.2 L10.2 L11.1 | length 0.1
  Top Layer w0.5: L10.2@33.276,16.98 L10.2@33.326,17.03
NetC41_2: C41.2 C42.2 L11.2 U804.5 U804.6
NetC45_1: C45.1 L12.1 U802.1 | length 2.5
  Top Layer w0.25: C45.1@28.994,32.863 28.997,32.866 L12.1@28.997,33.813
  Top Layer w0.42: U802.1@27.413,32.858 28.989,32.858 28.993,32.862 C45.1@28.994,32.863
NetC45_2: C45.2 U902.2 | length 1.2
  Top Layer w0.25: U902.2@31.204,32.863 U902.2@31.214,32.873
  Top Layer w0.42: C45.2@29.997,32.863 30,32.86 30.003,32.857 U902.2@31.207,32.857
NetC46_1: C46.1 L13.2 U901.5 | length 1.9
  Top Layer w0.25: C46.1@23.147,34.168 C46.1@23.162,34.168
  Top Layer w0.42: U901.5@21.289,34.168 22.347,34.168 23.143,34.168 C46.1@23.147,34.163
NetC46_2: C46.2 U802.3 | length 1.3
  Top Layer w0.25: C46.2@24.127,34.168 ccw(c24.152,34.193) C46.2@24.152,34.158
  Top Layer w0.42: C46.2@24.147,34.163 24.153,34.158 U802.3@25.463,34.158
NetC51_2: C51.2 L15.1 U805.8 | length 2.4
  Top Layer w0.42: L15.1@11.897,14.48 12.57,14.48 14.331,14.48
NetC52_2: C52.2 D1.1 L15.2 RFO.1 | length 2.7
  Top Layer w0.25: L15.2@11.21,14.495 L15.2@11.224,14.508
  Top Layer w0.3: RFO.1@8.404,14.483 RFO.1@8.407,14.48
  Top Layer w0.42: RFO.1@8.407,14.48 9.825,14.48 10.423,14.48 L15.2@11.072,14.48
NetC200_1: C200.1 FB200.2 R207.1 U200.3 | length 0.8
  Top Layer w0.3: FB200.2@67.612,47.385 67.62,47.377 R207.1@67.62,46.566
NetC202_1: C202.1 FB207.1 L200.2 U201.18 | length 6
  Top Layer w0.2: U201.18@62.539,17.052 62.539,17.527 63.322,18.31 L200.2@64.262,18.31
  Top Layer w0.5: C202.1@67.183,20.164 67.196,20.177 FB207.1@68.25,20.177
  Top Layer w0.7: L200.2@64.668,20.139 L200.2@64.694,20.164 64.705,20.175 C202.1@67.03,20.175
NetC203_1: C203.1 FB208.1 L201.2 U201.8 | length 4
  Top Layer w0.5: FB208.1@59.188,10.783 FB208.1@59.275,10.783 60.409,10.783 60.457,10.735 60.503,10.69 60.573,10.761 C203.1@60.579,10.766
  Top Layer w0.7: C203.1@60.528,10.806 62.533,10.806 62.977,10.806 L201.2@63.017,10.766
NetC205_1: C205.1 FB201.1 R200.2 U200.6 | length 1
  Top Layer w0.3: FB201.1@60.271,47.485 60.31,47.446 60.313,47.444 R200.2@60.313,46.538
NetC206_1: C206.1 FB202.2 R213.1 U202.3 | length 1.2
  Top Layer w0.2: FB202.2@57.401,47.287 57.964,46.724 R213.1@57.964,46.317
NetC207_1: C207.1 FB203.1 R203.2 U202.6 | length 1
  Top Layer w0.3: R203.2@50.187,46.341 50.187,46.353 50.187,47.262 FB203.1@50.206,47.281 FB203.1@50.213,47.288
NetC214_1: C214.1 L202.1 R19.1 | length 5.4
  Top Layer w0.25: R19.1@11.046,45.627 R19.1@11.046,45.711 ; C214.1@15.309,46.368 15.297,46.368 15.297,45.553 ccw(c15.373,45.553) L202.1@15.319,45.5
  Top Layer w0.42: R19.1@11.046,45.627 cw(c11.988,44.686) 11.988,46.017 14.421,46.017 ccw(c14.421,46.431) 14.714,46.139 cw(c15.28,45.572) 15.28,46.373 C214.1@15.297,46.373
NetC214_2: C214.2 U207.11 | length 1.8
  Top Layer w0.42: C214.2@16.639,46.382 17.062,46.805 U207.11@18.261,46.805
NetC215_1: C215.1 FB1.2 U207.6 U207.7 U207.8
NetC216_2: C216.2 R209.1 U201.3 | length 3.4
  Top Layer w0.2: 58.572,15.567 58.608,15.602 U201.3@61.089,15.602
  Top Layer w0.5: C216.2@58.547,15.186 58.559,15.199 58.564,15.203 58.564,15.211 R209.1@58.564,16.001
NetC217_2: C217.2 R210.1 U201.13 | length 3.4
  Top Layer w0.2: U201.13@63.989,15.602 66.919,15.602 66.929,15.592
  Top Layer w0.5: 66.929,15.592 C217.2@66.929,16.037
NetC218_1: C218.1 L202.2 R217.1 | length 1.7
  Top Layer w0.4: L202.2@15.293,44.322 15.293,43.371 15.293,42.755 ccw(c15.444,42.755) C218.1@15.337,42.648
NetC708_1: C708.1 U700.3 | length 1
  Top Layer w0.25: U700.3@41.585,42.564 C708.1@42.56,42.564
NetC708_2: C708.2 R701.1 | length 0.6
  Top Layer w0.25: C708.2@43.06,42.564 R701.1@43.66,42.564
NetC711_1: C711.1 C713.2 C813.2 C814.1 U902.5 | length 10.9
  Top Layer w0.35: C813.2@39.523,34.073 C813.2@39.623,34.073
  Top Layer w0.42: U902.5@33.507,32.857 35.131,32.857 ccw(c35.131,34.454) 36.26,33.325 36.267,33.332 cw(c38.063,31.536) 38.063,34.076 C814.1@38.906,34.076 ; C813.2@39.623,34.073 39.623,34.893 cw(c40.259,34.893) 39.809,35.342 ccw(c39.205,35.947) 40.06,35.947 C713.2@40.06,37.514 C711.1@40.06,38.289
  Top Layer w0.48: C814.1@38.906,34.076 39.62,34.076 C813.2@39.623,34.073
NetC711_2: C711.2 L706.2 U700.22 | length 1.9
  Top Layer w0.3: U700.22@39.935,40.914 39.935,40.438 40.06,40.313 L706.2@40.06,39.864
  Top Layer w0.42: C711.2@40.06,39.089 L706.2@40.06,39.864
NetC712_2: C712.2 L706.1 U700.21 | length 1.9
  Top Layer w0.3: L706.1@39.26,39.864 39.26,40.307 39.435,40.482 U700.21@39.435,40.914
  Top Layer w0.42: C712.2@39.26,39.089 L706.1@39.26,39.864
NetC716_2: C716.2 L708.1 R713.2 U700.1 | length 4.4
  MidLayer2 w0.5: v4(42.612,41.068) 42.612,42.914 42.91,43.212 v2(42.91,45.339)
NetC717_2: C717.2 L707.1 L708.2 U700.7
NetC801_2: C801.2 U800.8 | length 1.1
  Top Layer w0.25: U800.8@52.089,26.798 52.089,25.782 52.089,25.738 C801.2@52.092,25.735
NetC802_1: C802.1 U800.29 | length 1.5
  Top Layer w0.3: C802.1@46.484,29.098 46.522,29.06 46.569,29.014 46.935,29.014 47,28.948 U800.29@47.939,28.948
NetC802_2: C802.2 T1.4
NetC803_2: C803.2 U800.3 | length 1
  Top Layer w0.257: U800.3@49.589,26.798 49.589,26.323 49.696,26.216 C803.2@49.696,25.878
NetC804_1: C804.1 U800.5 | length 1
  Top Layer w0.257: U800.5@50.589,26.798 50.589,26.242 50.691,26.14 C804.1@50.691,25.878
NetC805_1: C805.1 U800.1 | length 1.2
  Top Layer w0.257: C805.1@48.139,25.798 C805.1@48.139,25.823 48.139,25.948 48.589,26.398 U800.1@48.589,26.798
NetC807_2: C807.2 U800.25 | length 1.6
  Top Layer w0.35: U800.25@47.939,30.973 C807.2@47.939,32.523
NetC809_2: C809.2 T800.3 | length 0.9
  Top Layer w0.42: T800.3@46.419,35.179 46.419,35.787 cw(c46.762,35.787) C809.2@46.52,36.029
NetC810_2: C810.2 T800.4 | length 0.8
  Top Layer w0.42: T800.4@45.351,36.25 45.645,36.25 ccw(c45.645,36.895) C810.2@46.101,36.439
NetC812_2: C812.2 U803.4
NetC813_1: C813.1 L801.2 | length 0.8
  Top Layer w0.25: L801.2@41.173,34.073 41.186,34.086 L801.2@41.198,34.098
  Top Layer w0.42: C813.1@40.423,34.073 L801.2@41.173,34.073
NetC815_1: C815.1 C842.1 L817.2 | length 5.9
  Top Layer w0.25: C815.1@11.325,32.238 ccw(c11.325,33.096) C815.1@11.37,32.239
  Top Layer w0.42: C815.1@11.319,32.155 C815.1@11.319,32.143 ccw(c11.319,32.41) 11.508,32.221 13.009,33.722 cw(c14.085,32.647) 14.085,34.168 C842.1@15.644,34.168 L817.2@16.361,34.168
NetC815_2: C815.2 D802.1 RFI.1 | length 2.4
  Top Layer w0.25: RFI.1@8.201,32.221 RFI.1@8.399,32.221 ; C815.2@10.519,32.227 C815.2@10.536,32.227 ; C815.2@10.524,32.228 cw(c10.524,32.173) C815.2@10.536,32.227 ; C815.2@10.563,32.212 ccw(c10.524,32.173) C815.2@10.536,32.227 ; C815.2@10.616,32.227 C815.2@10.536,32.227
  Top Layer w0.42: RFI.1@8.399,32.143 9.878,32.143 C815.2@10.424,32.143
NetC816_1: C816.1 U800.30 | length 1.5
  Top Layer w0.3: C816.1@46.484,28.298 46.844,28.298 46.994,28.448 U800.30@47.939,28.448
NetC816_2: C816.2 T1.3
NetC838_2: C838.2 FB801.2 Y800.4
NetC841_1: C841.1 L817.1 U901.2 | length 1.8
  Top Layer w0.42: L817.1@17.161,34.168 C841.1@17.904,34.168 U901.2@18.989,34.168
NetC901_1: C901.1 U900.8 | length 1
  Top Layer w0.25: U900.8@52.089,34.898 52.089,33.906 52.089,33.892 C901.1@52.092,33.889 ; C901.1@52.118,33.889 C901.1@52.118,33.906
NetC903_2: C903.2 U900.3 | length 1
  Top Layer w0.3: U900.3@49.589,34.898 49.589,34.423 49.722,34.291 C903.2@49.722,33.923
NetC904_1: C904.1 U900.5 | length 1
  Top Layer w0.3: U900.5@50.589,34.898 50.589,34.466 50.737,34.319 C904.1@50.737,33.923
NetC905_1: C905.1 U900.1 | length 1.2
  Top Layer w0.3: C905.1@48.139,33.923 48.139,34.048 48.589,34.498 U900.1@48.589,34.898
NetC907_2: C907.2 U900.25 | length 1.8
  Top Layer w0.257: U900.25@47.689,39.048 U900.25@47.939,39.048
  Top Layer w0.3: U900.25@47.939,39.048 C907.2@47.939,40.623
NetCONFIG_OK_1: CONFIG_OK.1 R105.1 | length 1.1
  Bottom Layer w0.5: CONFIG_OK.1@56.106,53.624 56.12,53.61 56.135,53.595 R105.1@56.135,52.551
NetD2_1: D2.1 FB3.2 | length 1.5
  Top Layer w0.65: FB3.2@16.598,9.304 17.599,9.304 D2.1@17.954,9.659
NetD5_1: D5.1 GPS.1 R19.2 | length 2.6
  Top Layer w0.25: GPS.1@8.112,43.929 ccw(c8.206,44.023) 8.206,43.89 GPS.1@8.399,43.89 ; R19.2@11.046,44.411 R19.2@11.046,44.527
  Top Layer w0.42: GPS.1@8.399,43.89 9.878,43.89 10.572,43.89
NetD800_1: D800.1 U800.9 | length 1.8
  Top Layer w0.2: U800.9@52.739,27.448 52.739,27.073 53.417,26.396 53.908,26.396 D800.1@53.921,26.396
NetD900_1: D900.1 U900.9 | length 1.5
  Top Layer w0.2: U900.9@52.739,35.548 52.739,35.223 53.364,34.598 D900.1@53.679,34.598 D900.1@53.689,34.598
NetDC5V_1: DC5V.1 R14.1 | length 1.1
  Bottom Layer w0.3: R14.1@50.16,52.555 50.16,53.597 50.174,53.611 DC5V.1@50.213,53.65
NetF200_1: F200.1 P1.1
NetF200_2: F200.2 L8.1
NetJ800_2: J800.2 T800.1 | length 9.4
  Top Layer w0.42: J800.2@38.685,27.918 v1(39.593,27.918)
  Bottom Layer w0.42: v1(39.593,27.918) 39.916,27.918 ccw(c39.916,28.695) 40.466,28.145 41.927,29.606 ccw(c41.118,30.415) 42.262,30.415 cw(c43.58,30.415) 42.648,31.347 v1(45.137,33.837)
NetL1_1: L1.1 U206.9 U206.10 U206.11
NetL3_1: L3.1 U804.1 | length 1.8
  Top Layer w0.3: U804.1@31.135,13.745 32.086,13.745 L3.1@32.701,13.13
NetL4_1: L4.1 R300.2 U804.9 U804.10 U804.11 U804.12 | length 3
  Top Layer w0.2: L4.1@27.073,13.111 R300.2@27.073,14.392
  Top Layer w0.25: 27.491,14.489 27.519,14.461 ; U804.9@28.235,15.245 U804.10@28.235,14.749 ; U804.12@28.239,13.721 28.235,13.725 U804.12@28.235,13.745 U804.11@28.235,14.245 U804.10@28.235,14.745 U804.10@28.235,14.749 ; U804.10@28.265,14.737 28.253,14.749 U804.10@28.235,14.749
  Top Layer w0.3: L4.1@26.997,13.035 L4.1@27.073,13.111
NetL200_1: L200.1 U201.20
NetL201_1: L201.1 U201.10 | length 2.4
  Top Layer w0.2: U201.10@63.339,14.152 64.668,12.824 L201.1@65.151,12.824
NetL707_2: L707.2 U700.9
